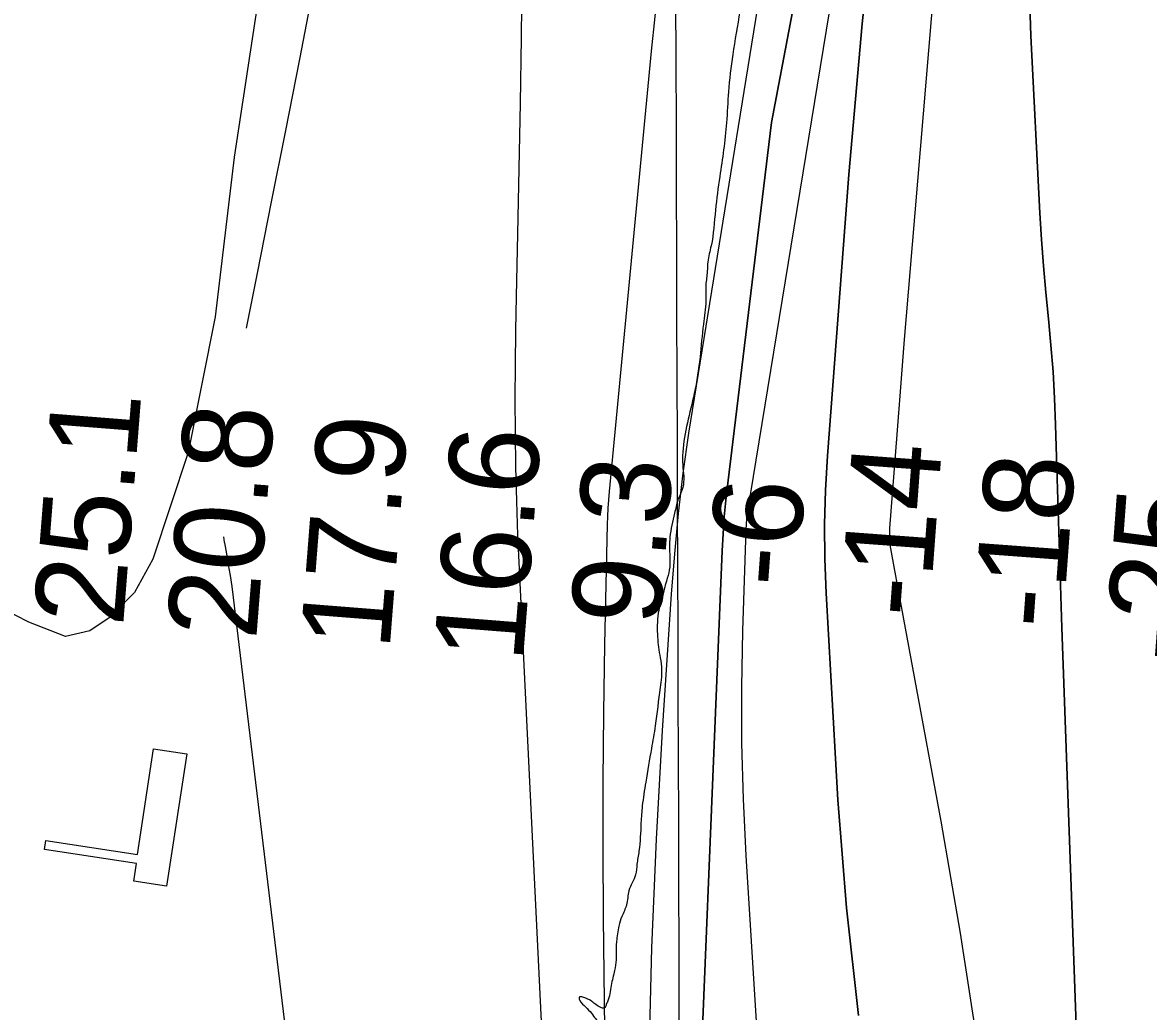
# Model space of a CAD drawing. Extents: x 3392644 to 3430565, y 576657 to 602123.
# Drawn here: x 3401526 to 3402367, y 591674 to 592413 of the extents above; entities that cross this region are included whole.
import ezdxf

# ---------------------------------------------------------------- set-up
doc = ezdxf.new("R2010")
doc.units = 0
for name, color, linetype in [('V-CHAN-DOCK', 7, 'Continuous'), ('V-GRID-MAJR', 7, 'Continuous'), ('V-RIVR-EDGE', 7, 'Continuous'), ('V-RIVR-RANG', 7, 'Continuous'), ('V-SITE-VEGE', 7, 'Continuous'), ('V-TOPO-DPTH', 7, 'Continuous'), ('V-TOPO-MINR', 7, 'Continuous'), ('V-TOPO-WATR', 7, 'Continuous')]:
    doc.layers.add(name, color=color, linetype=linetype)

msp = doc.modelspace()

# ---------------------------------------------------------------- linework, layer by layer
at = {"layer": 'V-CHAN-DOCK'}
msp.add_lwpolyline([(3401648.336, 591866.93), (3401633.22, 591768.096), (3401608.697, 591771.846), (3401610.7060000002, 591784.986), (3401542, 591795.4940000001), (3401543.04, 591802.301), (3401611.544, 591791.826), (3401623.608, 591870.713), (3401648.336, 591866.93)], dxfattribs=at)
at = {"layer": 'V-GRID-MAJR'}
msp.add_spline([(3402048.6720000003, 582063.4890000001), (3402028.4020000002, 588122.6730000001), (3402008.125, 594183.791), (3401987.849, 600244.93), (3401987.843, 600246.845)], degree=3, dxfattribs=at)
at = {"layer": 'V-RIVR-EDGE'}
for points in [[(3402941.001769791, 594701.1392732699), (3402930.8318199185, 594681.4123995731), (3402924.8153355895, 594670.8560152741), (3402918.4368935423, 594656.4243968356), (3402913.8473284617, 594652.9119917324), (3402910.315754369, 594649.7493458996), (3402909.956410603, 594646.9312314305), (3402909.9476974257, 594643.407499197), (3402910.6437306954, 594639.882024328), (3402906.0576508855, 594637.7791121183), (3402901.8283008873, 594637.4371947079), (3402902.5164922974, 594630.7403608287), (3402901.449788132, 594626.8668693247), (3402898.261874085, 594620.1796199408), (3402895.0774453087, 594614.9018634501), (3402892.2523602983, 594612.4422214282), (3402886.610903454, 594611.0466696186), (3402883.078458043, 594607.5316505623), (3402880.9546342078, 594603.6607730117), (3402879.883573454, 594598.025415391), (3402877.041933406, 594588.8706821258), (3402875.6202420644, 594583.9409422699), (3402871.0341622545, 594581.83803006), (3402867.5043307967, 594579.3801306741), (3402866.0896099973, 594577.2693766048), (3402866.0852534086, 594575.5075104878), (3402867.4860331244, 594571.9802929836), (3402865.72329569, 594571.6322763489), (3402861.8428336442, 594569.8799947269), (3402860.4228849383, 594565.6550013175), (3402855.110275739, 594554.7445011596), (3402849.4522638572, 594546.6538581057), (3402840.950869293, 594528.7037353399), (3402832.8123037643, 594514.9812199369), (3402823.968991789, 594501.2604471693), (3402815.1221945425, 594486.1301815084), (3402805.5750074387, 594472.7635245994), (3402800.9758578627, 594465.3750140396), (3402797.7879438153, 594458.6877646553), (3402795.302162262, 594450.9416529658), (3402792.4640074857, 594443.1964125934), (3402788.921977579, 594435.8052880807), (3402783.266579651, 594428.7717646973), (3402777.269264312, 594425.9675913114), (3402774.089192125, 594422.4517009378), (3402768.071836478, 594411.5429434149), (3402764.167848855, 594400.2765847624), (3402763.446547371, 594393.583236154), (3402762.033569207, 594392.1772285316), (3402754.6372167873, 594393.6050190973), (3402749.3481331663, 594392.2085959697), (3402746.517820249, 594387.634714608), (3402746.509107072, 594384.1109823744), (3402747.9142433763, 594382.3456309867), (3402747.9090154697, 594380.2313916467), (3402745.4424029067, 594380.2374908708), (3402738.748182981, 594380.6064191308), (3402736.6243591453, 594376.7355415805), (3402736.602576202, 594367.9262109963), (3402735.885631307, 594362.9947285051), (3402733.7652927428, 594360.533343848), (3402727.767106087, 594357.3767972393), (3402725.2882950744, 594352.4496713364), (3402723.159243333, 594346.4645544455), (3402719.9661013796, 594337.6630657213), (3402712.5253117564, 594321.1198218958), (3402704.0204319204, 594301.7602062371), (3402700.82990392, 594294.0158371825), (3402700.11121639, 594288.3796082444), (3402702.564759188, 594283.0879106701), (3402702.547332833, 594276.040446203), (3402700.415667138, 594268.9982096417), (3402687.3220935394, 594246.478562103), (3402678.4787815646, 594232.7577893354), (3402668.9211386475, 594215.1626537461), (3402660.42845726, 594200.7362632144), (3402648.3893893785, 594177.1568820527), (3402635.658644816, 594158.8648418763), (3402620.4421187, 594132.8266900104), (3402617.26291783, 594129.6631728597), (3402613.0361817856, 594130.3783751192), (3402610.214582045, 594129.328225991), (3402609.5063503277, 594127.9204757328), (3402609.5028650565, 594126.5109828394), (3402609.4924092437, 594122.2825041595), (3402607.376427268, 594121.5829856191), (3402603.146205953, 594120.888694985), (3402602.081244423, 594117.7199499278), (3402601.72102934, 594114.5494622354), (3402607.7026609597, 594111.0109176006), (3402608.7528100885, 594108.1893178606), (3402605.933824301, 594108.1962884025), (3402597.8335967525, 594109.9781948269), (3402594.292438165, 594102.9394435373), (3402590.7556361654, 594097.6625583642), (3402590.043047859, 594094.4929419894), (3402592.506175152, 594093.0773498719), (3402593.2048223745, 594090.608994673), (3402591.790972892, 594088.850613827), (3402588.9676305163, 594087.095718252), (3402584.385907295, 594086.7546721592), (3402582.2699253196, 594086.055153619), (3402582.2638260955, 594083.5885410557), (3402582.2594695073, 594081.8266749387), (3402582.6013869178, 594077.5973249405), (3402582.2420431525, 594074.7792104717), (3402577.2739653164, 594060.6964799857), (3402570.5431500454, 594046.2657328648), (3402562.761314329, 594034.304212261), (3402557.105045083, 594026.9183156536), (3402552.152650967, 594019.1783031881), (3402547.55001612, 594010.3802997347), (3402546.4763414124, 594003.687822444), (3402544.3507749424, 593999.112198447), (3402536.9335108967, 593992.083031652), (3402524.918839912, 593978.3701007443), (3402517.844364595, 593967.4639571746), (3402508.290206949, 593951.2783144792), (3402494.8355469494, 593925.2358060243), (3402485.976551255, 593905.1723152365), (3402481.7001501, 593885.8022437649), (3402480.964036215, 593873.1185503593), (3402479.8772917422, 593861.1404747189), (3402477.4089365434, 593860.4418274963), (3402474.9292542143, 593855.1623283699), (3402471.7343696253, 593845.656093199), (3402471.0069689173, 593836.4961320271), (3402466.7575786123, 593828.0496304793), (3402461.451068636, 593819.6057428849), (3402459.318531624, 593812.2111331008), (3402457.5218127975, 593798.1205607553), (3402452.9200492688, 593789.6749305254), (3402449.030874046, 593784.3989166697), (3402445.8447026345, 593778.4164137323), (3402438.753672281, 593760.8151789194), (3402434.4973114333, 593749.5496915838), (3402433.07997668, 593746.3818178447), (3402433.059936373, 593738.2772337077), (3402432.3395062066, 593731.9362583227), (3402430.2174250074, 593728.7701272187), (3402423.4935802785, 593717.158365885), (3402419.612246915, 593715.0537110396), (3402417.8399249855, 593710.8295889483), (3402417.4779672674, 593706.9543548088), (3402416.754923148, 593699.5562597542), (3402415.679505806, 593692.1590360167), (3402409.663892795, 593681.9550249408), (3402400.4568804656, 593663.6542715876), (3402383.8064645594, 593627.753154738), (3402369.6313743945, 593595.3696708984), (3402360.421748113, 593576.0117978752), (3402343.4128597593, 593537.6449397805), (3402326.403971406, 593499.2780816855), (3402307.5852944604, 593441.5350528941), (3402291.603900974, 593391.1848912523), (3402279.8997799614, 593360.5571743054), (3402271.021615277, 593332.7414726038), (3402263.9210004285, 593311.2641323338), (3402259.3035531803, 593296.4757840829), (3402256.4767255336, 593293.3113956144), (3402250.8352686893, 593291.9158438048), (3402249.062075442, 593287.33934849), (3402248.7009890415, 593283.8164875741), (3402247.2697132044, 593275.010642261), (3402246.879873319, 593259.8594649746), (3402245.8018420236, 593251.4051215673), (3402239.7705452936, 593234.8583924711), (3402233.7409911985, 593219.0164098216), (3402225.9251740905, 593193.3123335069), (3402216.6824377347, 593160.5642779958), (3402196.051358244, 593082.387958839), (3402192.855602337, 593072.5293504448), (3402189.2883042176, 593054.9194024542), (3402186.437950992, 593042.2409369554), (3402183.2238974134, 593024.9824908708), (3402180.377900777, 593014.0658914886), (3402177.181273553, 593003.8549098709), (3402173.2668301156, 592988.3600725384), (3402168.635441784, 592967.9337527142), (3402164.0040534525, 592947.5074328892), (3402158.300733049, 592921.0933822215), (3402152.262465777, 592901.7276673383), (3402148.361963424, 592891.8708015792), (3402148.3497649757, 592886.9375764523), (3402145.840457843, 592869.6773877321), (3402139.753396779, 592830.5787723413), (3402138.305565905, 592815.0778357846), (3402134.744367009, 592799.9345003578), (3402130.117335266, 592781.2700466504), (3402122.998422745, 592752.3928686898), (3402115.1512381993, 592714.0033563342), (3402112.290429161, 592697.0964121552), (3402108.005314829, 592674.2026084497), (3402103.0067408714, 592647.7868151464), (3402096.5917034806, 592618.5555213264), (3402093.037475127, 592606.2311716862), (3402086.6337648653, 592581.5807297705), (3402081.6595878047, 592565.031386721), (3402076.6732122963, 592543.5488185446), (3402073.8150172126, 592527.6989940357), (3402069.876176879, 592502.3377064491), (3402067.7122724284, 592482.257660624), (3402064.833165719, 592457.9508787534), (3402064.4311273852, 592437.8664763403), (3402061.924434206, 592421.66340729), (3402056.5595459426, 592389.6105137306), (3402053.3193528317, 592361.7808709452), (3402051.8523529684, 592338.5277234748), (3402046.81979762, 592298.3693744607), (3402043.5865750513, 592273.358717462), (3402040.3489958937, 592246.5861943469), (3402037.8527585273, 592234.6116039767), (3402037.48295895, 592227.5650108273), (3402036.4005710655, 592217.3488013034), (3402036.3709462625, 592205.3681117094), (3402034.5663855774, 592188.1061803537), (3402032.0387807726, 592163.4461539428), (3402027.7432106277, 592136.3238715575), (3402019.1773385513, 592092.2981302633), (3402019.153812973, 592082.7840532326), (3402019.837647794, 592074.3253532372), (3402019.828063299, 592070.4492477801), (3402019.467848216, 592067.2787600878), (3402015.5656032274, 592056.7171478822), (3402013.074593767, 592046.8567968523), (3402009.5064243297, 592028.8944756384), (3402009.470700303, 592014.4471734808), (3402009.093058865, 592004.2292213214), (3402006.958779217, 591996.1298650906), (3402003.7569240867, 591983.8046441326), (3402001.2667859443, 591974.2966663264), (3402000.165229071, 591956.3282458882), (3402001.888757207, 591940.8194674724), (3402003.2764671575, 591932.006651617), (3402002.1810095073, 591916.5048437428), (3401998.5867005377, 591887.9713258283), (3401995.7258915, 591871.0643816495), (3401991.434677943, 591845.7039653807), (3401988.9244994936, 591828.091403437), (3401987.9213314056, 591815.3849305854)], [(3401987.9213314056, 591815.3849305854), (3401986.374240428, 591794.2696732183), (3401984.9403506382, 591784.4067082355), (3401983.8640619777, 591776.657111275), (3401978.9012120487, 591764.6886201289), (3401977.1132064, 591754.1217800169), (3401973.567691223, 591745.3211626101), (3401971.4360255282, 591738.2789260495), (3401969.6454059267, 591726.6549662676), (3401969.2668931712, 591716.0846408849), (3401969.2590513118, 591712.9132818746), (3401968.1827626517, 591705.1636849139), (3401965.688267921, 591693.8938409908), (3401962.838786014, 591681.5677487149), (3401961.7755671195, 591679.1037501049), (3401961.420579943, 591678.0475017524), (3401960.3608463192, 591676.9929960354), (3401957.895105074, 591677.351468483), (3401951.2113409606, 591681.9488754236), (3401944.5240915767, 591685.1367894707), (3401941.7051057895, 591685.1437600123), (3401942.052251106, 591683.0286493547), (3401946.620033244, 591677.7317238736), (3401950.8371847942, 591673.1404161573), (3401957.5113644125, 591664.6669037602), (3401962.0843744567, 591661.4842176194), (3401967.720603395, 591660.7655300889), (3401970.1819880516, 591658.6451915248), (3401967.3473185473, 591652.309444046), (3401963.8201010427, 591650.9086643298), (3401963.465113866, 591649.8524159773), (3401963.457272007, 591646.681056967), (3401964.845853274, 591638.2206143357), (3401962.369656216, 591634.3506081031), (3401959.531501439, 591626.6053677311), (3401959.5245308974, 591623.7863819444), (3401959.849893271, 591612.8619407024), (3401959.83508087, 591606.8715959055), (3401960.503231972, 591592.0701778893), (3401959.085897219, 591588.9023041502), (3401954.8548045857, 591587.8556402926), (3401949.5665922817, 591586.8115903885), (3401948.5025020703, 591583.995218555), (3401948.4842043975, 591576.5953808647), (3401949.8928259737, 591576.2395223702), (3401955.530797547, 591576.2255812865), (3401957.2883070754, 591574.4593585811), (3401957.27872258, 591570.5832531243), (3401962.5102992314, 591548.7230435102), (3401966.3280264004, 591525.1044530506), (3401969.443621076, 591502.5447248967), (3401975.3869147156, 591483.5017584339), (3401978.862724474, 591464.112517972), (3401980.895059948, 591430.9842070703), (3401982.5889632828, 591403.4947390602), (3401980.7844025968, 591386.2328077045), (3401978.650122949, 591378.1334514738), (3401977.190093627, 591357.6992897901), (3401976.752331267, 591323.1675852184), (3401976.330252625, 591294.9785986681), (3401975.6089511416, 591288.2852500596), (3401977.3481629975, 591279.1191896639), (3401981.890676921, 591263.6034407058), (3401986.4410327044, 591251.2590507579), (3401992.0302104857, 591231.5122091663), (3401995.162360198, 591215.6475722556), (3402000.3695399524, 591183.9209123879), (3402003.4642230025, 591152.904226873), (3402003.0177474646, 591114.8487900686), (3402003.616193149, 591071.8575141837), (3402003.1975997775, 591045.0780205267), (3402005.2621740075, 591024.987518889), (3402008.735369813, 591004.5411587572), (3402015.3502998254, 590972.1062671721), (3402020.9281504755, 590947.7785736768), (3402026.4946739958, 590918.8700282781), (3402035.9503727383, 590895.2374967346), (3402040.4928866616, 590879.7217477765), (3402044.68738395, 590865.968736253), (3402045.0005478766, 590850.1110698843), (3402048.467644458, 590827.198097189), (3402058.6080493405, 590795.4592388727), (3402062.094314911, 590780.2984770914), (3402068.73364182, 590757.7300357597), (3402076.0733585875, 590733.3979856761), (3402090.056758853, 590688.2593603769), (3402093.19849306, 590676.2708289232), (3402097.73490776, 590658.2884674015), (3402098.0637554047, 590648.7735190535), (3402100.858344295, 590638.9000982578), (3402105.0606834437, 590628.3184457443)]]:
    msp.add_spline(points, degree=3, dxfattribs=at)
at = {"layer": 'V-SITE-VEGE'}
msp.add_lwpolyline([(3401707.804, 592470.371), (3401683.865, 592312.9720000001), (3401669.582, 592193.601), (3401649.487, 592092.286), (3401623.133, 592012.568), (3401609.33, 591987.496), (3401591.078, 591969.058), (3401575.8510000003, 591958.953), (3401557.773, 591954.7220000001), (3401530.381, 591965.335), (3401500.95, 591980.256)], dxfattribs=at)
at = {"layer": 'V-TOPO-DPTH'}
for points in [[(3402200.914730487, 592946.7586107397), (3402085.380665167, 592338.7008568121), (3402052.7727680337, 592069.1801388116), (3402051.4005930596, 592056.587293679), (3402050.2280213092, 592043.9782718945), (3402049.354854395, 592031.3449851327), (3402048.6812907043, 592018.6955217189), (3402026.940177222, 591493.0218269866), (3402026.170554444, 591463.746747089), (3402025.9881179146, 591434.4768427), (3402026.6864607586, 591405.2147015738), (3402027.971989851, 591375.9577359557), (3402030.2512651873, 591346.7724878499), (3402033.264669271, 591317.6773761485), (3402037.379266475, 591288.7174690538), (3402042.2279924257, 591259.8476983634), (3402069.3611059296, 591115.1590404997), (3402081.620996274, 591052.1971110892), (3402094.4613117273, 590989.3579844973), (3402108.172264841, 590926.7030621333)], [(3402108.172264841, 590926.7030621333), (3402094.4613117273, 590989.3579844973), (3402081.620996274, 591052.1971110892), (3402069.3611059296, 591115.1590404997), (3402042.2279924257, 591259.8476983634), (3402037.379266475, 591288.7174690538), (3402033.264669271, 591317.6773761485), (3402030.2512651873, 591346.7724878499), (3402027.971989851, 591375.9577359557), (3402026.6864607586, 591405.2147015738), (3402025.9881179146, 591434.4768427), (3402026.170554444, 591463.746747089), (3402026.940177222, 591493.0218269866), (3402048.6812907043, 592018.6955217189), (3402049.354854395, 592031.3449851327), (3402050.2280213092, 592043.9782718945), (3402051.4005930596, 592056.587293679), (3402052.7727680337, 592069.1801388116), (3402085.380665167, 592338.7008568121), (3402200.914730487, 592946.7586107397)], [(3402150.5984855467, 591671.3993649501), (3402141.618506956, 591751.8489736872), (3402135.115501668, 591832.633310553), (3402126.2858237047, 591986.9737898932), (3402125.3319524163, 592012.6844940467), (3402125.065253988, 592038.3885486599), (3402125.8293148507, 592064.082628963), (3402127.280548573, 592089.7700597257), (3402143.3807819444, 592299.8212366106), (3402153.355532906, 592412.438992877), (3402165.1024087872, 592524.8503268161)], [(3402150.5984855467, 591671.3993649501), (3402141.618506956, 591751.8489736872), (3402135.115501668, 591832.633310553), (3402126.2858237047, 591986.9737898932), (3402125.3319524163, 592012.6844940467), (3402125.065253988, 592038.3885486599), (3402125.8293148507, 592064.082628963), (3402127.280548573, 592089.7700597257), (3402143.3807819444, 592299.8212366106), (3402153.355532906, 592412.438992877), (3402165.1024087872, 592524.8503268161)], [(3402006.5459997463, 592495.9372565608), (3401995.6325773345, 592392.0817369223), (3401964.145147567, 592062.9417480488), (3401963.62457059, 592056.7870882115), (3401963.194334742, 592050.6271157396), (3401962.8996105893, 592044.4591743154), (3401962.695227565, 592038.2859202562), (3401960.711910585, 591948.5655973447), (3401959.843778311, 591897.526860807), (3401959.3223328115, 591846.4863485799), (3401959.3209174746, 591795.4431728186), (3401959.6661889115, 591744.3982213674), (3401964.115790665, 591369.1838692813), (3401964.554176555, 591344.122876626), (3401965.1806947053, 591319.0676487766), (3401966.089411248, 591294.0210681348), (3401967.186260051, 591268.9802522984), (3401977.8742352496, 591052.8318883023), (3401983.2324119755, 590968.6679456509), (3401990.1753502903, 590884.6576055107)], [(3402276.7074627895, 592489.5042080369), (3402279.425348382, 592403.5161033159), (3402286.153307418, 592271.1203369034), (3402287.330573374, 592251.3220461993), (3402288.7349970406, 592231.5418529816), (3402290.480157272, 592211.7888059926), (3402292.4524752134, 592192.0538564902), (3402294.3573966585, 592172.3162428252), (3402295.945565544, 592152.5569959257), (3402297.058605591, 592132.7652991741), (3402297.85489308, 592112.9519691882), (3402298.53623889, 592088.756650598), (3402299.471383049, 592056.8305662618), (3402300.4546143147, 592024.9060173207), (3402301.50997624, 591992.983771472), (3402302.6134252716, 591961.063061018), (3402320.8567761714, 591450.0387901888)], [(3402320.8567761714, 591450.0387901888), (3402302.6134252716, 591961.063061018), (3402301.50997624, 591992.983771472), (3402300.4546143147, 592024.9060173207), (3402299.471383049, 592056.8305662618), (3402298.53623889, 592088.756650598), (3402297.85489308, 592112.9519691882), (3402297.058605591, 592132.7652991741), (3402295.945565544, 592152.5569959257), (3402294.3573966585, 592172.3162428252), (3402292.4524752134, 592192.0538564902), (3402290.480157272, 592211.7888059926), (3402288.7349970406, 592231.5418529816), (3402287.330573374, 592251.3220461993), (3402286.153307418, 592271.1203369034), (3402279.425348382, 592403.5161033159), (3402276.7074627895, 592489.5042080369)]]:
    msp.add_lwpolyline(points, dxfattribs=at)
at = {"layer": 'V-TOPO-MINR'}
for points in [[(3402183.6770796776, 594038.2732107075), (3402172.773929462, 594009.1978548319), (3402162.492718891, 593979.8777509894), (3401907.939166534, 593214.5772326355), (3401900.2759599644, 593190.797551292), (3401892.9113497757, 593166.9287901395), (3401885.994634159, 593142.9264092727), (3401879.3765149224, 593118.834948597), (3401873.2059944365, 593094.6247360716), (3401867.333201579, 593070.3453937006), (3401861.9070001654, 593045.9623565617), (3401856.7785263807, 593021.5101895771), (3401855.569682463, 593015.4711367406), (3401850.0809432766, 592987.9434684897), (3401844.619786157, 592960.4103509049), (3401839.2000021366, 592932.8690593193), (3401833.8078001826, 592905.3223183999), (3401742.9881095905, 592439.5026137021), (3401732.554832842, 592386.1326460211), (3401722.0857699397, 592332.7697177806), (3401711.5630278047, 592279.4173487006), (3401701.0044995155, 592226.0720190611), (3401692.879798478, 592185.1313582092)], [(3402166.3477562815, 592989.6805613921), (3402023.333321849, 592106.6881891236), (3402019.3003042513, 592076.6578368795), (3402015.7437181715, 592046.5768775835), (3402012.9017793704, 592016.4200077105), (3402010.536272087, 591986.2125307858), (3402003.773892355, 591884.3399300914), (3401999.196925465, 591803.1313316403), (3401995.7015482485, 591721.8870109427), (3401993.828555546, 591640.5891068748), (3401993.0371525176, 591559.2554805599), (3401993.092471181, 591340.1100279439), (3401993.178405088, 591329.2430207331), (3401993.3751991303, 591318.3788706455), (3401993.7382833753, 591307.5190062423), (3401994.212227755, 591296.6619989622), (3401997.8585246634, 591225.6198225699), (3402001.02583153, 591179.3292255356), (3402005.2396910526, 591133.1521294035), (3402011.0233795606, 591087.1452846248), (3402017.8536207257, 591041.251940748), (3402028.254734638, 590978.702703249), (3402035.2523009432, 590938.4310933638), (3402042.638547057, 590898.2338251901)], [(3402215.841390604, 592954.9003695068), (3402067.2094217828, 592046.8719856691), (3402066.8425716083, 592042.7127385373), (3402066.5811661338, 592038.5455352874), (3402066.3900571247, 592034.3730279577), (3402063.887532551, 591958.804393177), (3402063.097614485, 591916.8522597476), (3402063.1057268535, 591874.9116715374), (3402064.3108848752, 591832.9884011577), (3402066.314073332, 591791.0766759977), (3402094.6532840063, 591334.8446766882)], [(3402247.3836600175, 592922.4136522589), (3402190.522629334, 592247.4907204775), (3402187.571420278, 592212.0152467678), (3402184.6699195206, 592176.5357605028), (3402181.8429812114, 592141.0502554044), (3402179.065751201, 592105.5607377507), (3402173.6726296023, 592035.6997454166), (3402173.6028775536, 592034.0118143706), (3402173.6041240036, 592033.4484252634), (3402173.6795803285, 592028.7926742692), (3402173.799942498, 592026.0088458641), (3402174.019785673, 592023.235610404), (3402174.388850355, 592020.4782643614), (3402174.857396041, 592017.7315112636), (3402175.3955278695, 592014.9916976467), (3402175.926288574, 592012.2504722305), (3402176.445992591, 592009.507129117), (3402176.9583254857, 592006.7623742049), (3402212.062970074, 591816.5690207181), (3402226.428971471, 591732.9130582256), (3402239.400671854, 591649.0591442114)], [(3402165.1024087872, 592524.8503268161), (3402153.355532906, 592412.438992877), (3402143.3807819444, 592299.8212366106), (3402127.280548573, 592089.7700597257), (3402125.8293148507, 592064.082628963), (3402125.065253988, 592038.3885486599), (3402125.3319524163, 592012.6844940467), (3402126.2858237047, 591986.9737898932), (3402135.115501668, 591832.633310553), (3402141.618506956, 591751.8489736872), (3402150.5984855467, 591671.3993649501)], [(3402006.5459997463, 592495.9372565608), (3401995.6325773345, 592392.0817369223), (3401964.145147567, 592062.9417480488), (3401963.62457059, 592056.7870882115), (3401963.194334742, 592050.6271157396), (3401962.8996105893, 592044.4591743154), (3401962.695227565, 592038.2859202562), (3401960.711910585, 591948.5655973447), (3401959.843778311, 591897.526860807), (3401959.3223328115, 591846.4863485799), (3401959.3209174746, 591795.4431728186), (3401959.6661889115, 591744.3982213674), (3401964.115790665, 591369.1838692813), (3401964.554176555, 591344.122876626), (3401965.1806947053, 591319.0676487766), (3401966.089411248, 591294.0210681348), (3401967.186260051, 591268.9802522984), (3401977.8742352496, 591052.8318883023), (3401983.2324119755, 590968.6679456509), (3401990.1753502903, 590884.6576055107)], [(3402276.7074627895, 592489.5042080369), (3402279.425348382, 592403.5161033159), (3402286.153307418, 592271.1203369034), (3402287.330573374, 592251.3220461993), (3402288.7349970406, 592231.5418529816), (3402290.480157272, 592211.7888059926), (3402292.4524752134, 592192.0538564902), (3402294.3573966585, 592172.3162428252), (3402295.945565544, 592152.5569959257), (3402297.058605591, 592132.7652991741), (3402297.85489308, 592112.9519691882), (3402298.53623889, 592088.756650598), (3402299.471383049, 592056.8305662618), (3402300.4546143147, 592024.9060173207), (3402301.50997624, 591992.983771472), (3402302.6134252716, 591961.063061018), (3402320.8567761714, 591450.0387901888)], [(3401898.946307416, 592451.0517403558), (3401898.2773869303, 592402.1645677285), (3401897.5072262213, 592353.2791473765), (3401896.5852051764, 592304.3963554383), (3401895.5619439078, 592255.5153157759), (3401894.508816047, 592208.6840545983), (3401894.0586279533, 592183.2191686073), (3401893.771659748, 592157.7532279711), (3401893.7295213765, 592132.2857053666), (3401893.850602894, 592106.8171281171), (3401894.244431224, 592081.3521554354), (3401894.8386025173, 592055.893041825), (3401895.733288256, 592030.4427168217), (3401896.8283169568, 592004.9982508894), (3401923.1078588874, 591467.2142838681)], [(3401675.8207681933, 592029.1044409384), (3401676.406682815, 592025.2731897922), (3401676.5253450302, 592024.6206556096), (3401677.980705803, 592016.4691087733), (3401679.401175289, 592008.3116014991), (3401680.7693078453, 592000.1451535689), (3401682.1025491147, 591991.9727452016), (3401765.8551486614, 591299.0722258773), (3401767.3352383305, 591274.288312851), (3401777.6937299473, 591089.6539216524), (3401783.3508998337, 590997.885167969), (3401789.683309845, 590906.1667832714)]]:
    msp.add_lwpolyline(points, dxfattribs=at)
at = {"layer": 'V-TOPO-WATR'}
msp.add_lwpolyline([(3402200.914730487, 592946.7586107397), (3402085.380665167, 592338.7008568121), (3402052.7727680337, 592069.1801388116), (3402051.4005930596, 592056.587293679), (3402050.2280213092, 592043.9782718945), (3402049.354854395, 592031.3449851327), (3402048.6812907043, 592018.6955217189), (3402026.940177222, 591493.0218269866), (3402026.170554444, 591463.746747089), (3402025.9881179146, 591434.4768427), (3402026.6864607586, 591405.2147015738), (3402027.971989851, 591375.9577359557), (3402030.2512651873, 591346.7724878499), (3402033.264669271, 591317.6773761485), (3402037.379266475, 591288.7174690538), (3402042.2279924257, 591259.8476983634), (3402069.3611059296, 591115.1590404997), (3402081.620996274, 591052.1971110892), (3402094.4613117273, 590989.3579844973), (3402108.172264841, 590926.7030621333)], dxfattribs=at)

# ---------------------------------------------------------------- texts
at = {"layer": 'V-RIVR-RANG'}
for s, height, rotation, p in [('25.1', 67.00000000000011, 85.49832571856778, (3401600.716371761, 591961.5367360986)), ('20.8', 67.00000000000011, 85.49832571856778, (3401700.2410394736, 591951.5620440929)), ('17.9', 67.00000000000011, 85.49832571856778, (3401799.930335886, 591943.6910783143)), ('16.6', 67.00000000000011, 85.49832571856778, (3401899.5161143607, 591934.5052836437)), ('-14', 67.00000000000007, 85.7783888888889, (3402203.382124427, 591967.8323427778)), ('9.3', 67.00000000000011, 85.49832571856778, (3402001.9796915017, 591961.8717321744)), ('-18', 67.00000000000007, 85.7783888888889, (3402303.0348705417, 591959.4351512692)), ('-6', 67.00000000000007, 85.7783888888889, (3402104.7789482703, 591990.4349814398)), ('-25', 67.00000000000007, 85.7783888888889, (3402401.424449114, 591933.9388104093))]:
    msp.add_text(s, height=height, rotation=rotation, dxfattribs=at).set_placement(p)

doc.saveas('drawing.dxf')
